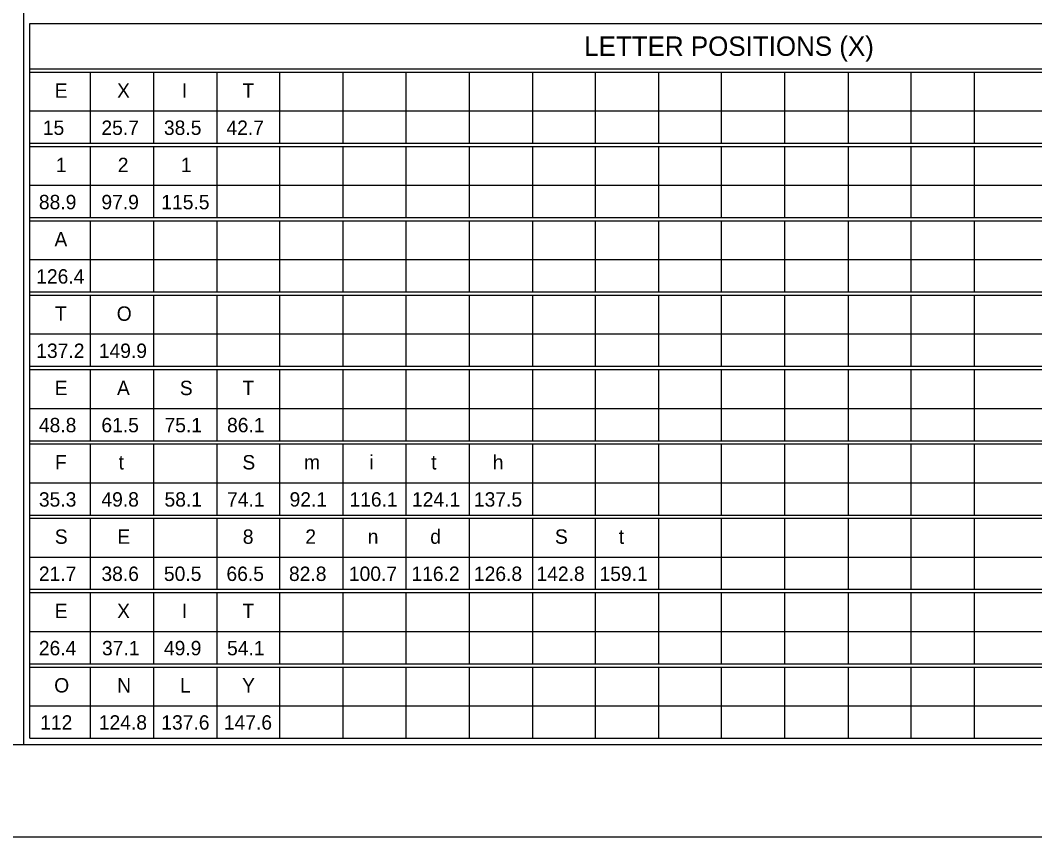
# Model space of a CAD drawing. Extents: x 2149934 to 2150188, y 145114 to 145238.
# Drawn here: x 2150076.2 to 2150112.58, y 145114.09 to 145143.36 of the extents above; entities that cross this region are included whole.
import ezdxf

# ---------------------------------------------------------------- set-up
doc = ezdxf.new("R2010")
doc.units = 0
for name, color, linetype in [('BORDER', 7, 'Continuous'), ('Level 1', 7, 'Continuous'), ('PDF', 7, 'Continuous')]:
    doc.layers.add(name, color=color, linetype=linetype)

msp = doc.modelspace()

# ---------------------------------------------------------------- linework, layer by layer
at = {"layer": 'BORDER'}
for p, q in [((2150017.557, 145117.388), (2150171.536, 145117.388)), ((2150010.458, 145114.088), (2150174.061, 145114.088))]:
    msp.add_line(p, q, dxfattribs=at)
at = {"layer": 'Level 1'}
for p, q in [((2150076.316, 145216.512), (2150076.316, 145117.388)), ((2150076.548, 145143.244), (2150134.843, 145143.244)), ((2150076.548, 145117.62), (2150076.548, 145143.244)), ((2150076.548, 145141.621), (2150134.843, 145141.621)), ((2150076.548, 145141.505), (2150134.843, 145141.505)), ((2150078.704, 145141.505), (2150078.704, 145138.954)), ((2150080.977, 145141.505), (2150080.977, 145138.954)), ((2150083.25, 145141.505), (2150083.25, 145138.954)), ((2150085.499, 145141.505), (2150085.499, 145138.954)), ((2150087.772, 145141.505), (2150087.772, 145138.954)), ((2150090.021, 145141.505), (2150090.021, 145138.954)), ((2150092.294, 145141.505), (2150092.294, 145138.954)), ((2150094.566, 145141.505), (2150094.566, 145138.954)), ((2150096.816, 145141.505), (2150096.816, 145138.954)), ((2150099.088, 145141.505), (2150099.088, 145138.954)), ((2150101.337, 145141.505), (2150101.337, 145138.954)), ((2150103.61, 145141.505), (2150103.61, 145138.954)), ((2150105.883, 145141.505), (2150105.883, 145138.954)), ((2150108.132, 145141.505), (2150108.132, 145138.954)), ((2150110.405, 145141.505), (2150110.405, 145138.954)), ((2150076.548, 145140.114), (2150126.185, 145140.114)), ((2150076.548, 145138.954), (2150134.843, 145138.954)), ((2150076.548, 145138.838), (2150134.843, 145138.838)), ((2150078.704, 145138.838), (2150078.704, 145136.288)), ((2150080.977, 145138.838), (2150080.977, 145136.288)), ((2150083.25, 145138.838), (2150083.25, 145136.288)), ((2150085.499, 145138.838), (2150085.499, 145136.288)), ((2150087.772, 145138.838), (2150087.772, 145136.288)), ((2150090.021, 145138.838), (2150090.021, 145136.288)), ((2150092.294, 145138.838), (2150092.294, 145136.288)), ((2150094.566, 145138.838), (2150094.566, 145136.288)), ((2150096.816, 145138.838), (2150096.816, 145136.288)), ((2150099.088, 145138.838), (2150099.088, 145136.288)), ((2150101.337, 145138.838), (2150101.337, 145136.288)), ((2150103.61, 145138.838), (2150103.61, 145136.288)), ((2150105.883, 145138.838), (2150105.883, 145136.288)), ((2150108.132, 145138.838), (2150108.132, 145136.288)), ((2150110.405, 145138.838), (2150110.405, 145136.288)), ((2150076.548, 145137.447), (2150126.185, 145137.447)), ((2150076.548, 145136.288), (2150134.843, 145136.288)), ((2150076.548, 145136.172), (2150134.843, 145136.172)), ((2150078.704, 145136.172), (2150078.704, 145133.621)), ((2150080.977, 145136.172), (2150080.977, 145133.621)), ((2150083.25, 145136.172), (2150083.25, 145133.621)), ((2150085.499, 145136.172), (2150085.499, 145133.621)), ((2150087.772, 145136.172), (2150087.772, 145133.621)), ((2150090.021, 145136.172), (2150090.021, 145133.621)), ((2150092.294, 145136.172), (2150092.294, 145133.621)), ((2150094.566, 145136.172), (2150094.566, 145133.621)), ((2150096.816, 145136.172), (2150096.816, 145133.621)), ((2150099.088, 145136.172), (2150099.088, 145133.621)), ((2150101.337, 145136.172), (2150101.337, 145133.621)), ((2150103.61, 145136.172), (2150103.61, 145133.621)), ((2150105.883, 145136.172), (2150105.883, 145133.621)), ((2150108.132, 145136.172), (2150108.132, 145133.621)), ((2150110.405, 145136.172), (2150110.405, 145133.621)), ((2150076.548, 145134.78), (2150126.185, 145134.78)), ((2150076.548, 145133.621), (2150134.843, 145133.621)), ((2150076.548, 145133.505), (2150134.843, 145133.505)), ((2150078.704, 145133.505), (2150078.704, 145130.954)), ((2150080.977, 145133.505), (2150080.977, 145130.954)), ((2150083.25, 145133.505), (2150083.25, 145130.954)), ((2150085.499, 145133.505), (2150085.499, 145130.954)), ((2150087.772, 145133.505), (2150087.772, 145130.954)), ((2150090.021, 145133.505), (2150090.021, 145130.954)), ((2150092.294, 145133.505), (2150092.294, 145130.954)), ((2150094.566, 145133.505), (2150094.566, 145130.954)), ((2150096.816, 145133.505), (2150096.816, 145130.954)), ((2150099.088, 145133.505), (2150099.088, 145130.954)), ((2150101.337, 145133.505), (2150101.337, 145130.954)), ((2150103.61, 145133.505), (2150103.61, 145130.954)), ((2150105.883, 145133.505), (2150105.883, 145130.954)), ((2150108.132, 145133.505), (2150108.132, 145130.954)), ((2150110.405, 145133.505), (2150110.405, 145130.954)), ((2150076.548, 145132.113), (2150126.185, 145132.113)), ((2150076.548, 145130.954), (2150134.843, 145130.954)), ((2150076.548, 145130.838), (2150134.843, 145130.838)), ((2150078.704, 145130.838), (2150078.704, 145128.287)), ((2150080.977, 145130.838), (2150080.977, 145128.287)), ((2150083.25, 145130.838), (2150083.25, 145128.287)), ((2150085.499, 145130.838), (2150085.499, 145128.287)), ((2150087.772, 145130.838), (2150087.772, 145128.287)), ((2150090.021, 145130.838), (2150090.021, 145128.287)), ((2150092.294, 145130.838), (2150092.294, 145128.287)), ((2150094.566, 145130.838), (2150094.566, 145128.287)), ((2150096.816, 145130.838), (2150096.816, 145128.287)), ((2150099.088, 145130.838), (2150099.088, 145128.287)), ((2150101.337, 145130.838), (2150101.337, 145128.287)), ((2150103.61, 145130.838), (2150103.61, 145128.287)), ((2150105.883, 145130.838), (2150105.883, 145128.287)), ((2150108.132, 145130.838), (2150108.132, 145128.287)), ((2150110.405, 145130.838), (2150110.405, 145128.287)), ((2150076.548, 145129.447), (2150126.185, 145129.447)), ((2150076.548, 145128.287), (2150134.843, 145128.287)), ((2150076.548, 145128.171), (2150134.843, 145128.171)), ((2150078.704, 145128.171), (2150078.704, 145125.62)), ((2150080.977, 145128.171), (2150080.977, 145125.62)), ((2150083.25, 145128.171), (2150083.25, 145125.62)), ((2150085.499, 145128.171), (2150085.499, 145125.62)), ((2150087.772, 145128.171), (2150087.772, 145125.62)), ((2150090.021, 145128.171), (2150090.021, 145125.62)), ((2150092.294, 145128.171), (2150092.294, 145125.62)), ((2150094.566, 145128.171), (2150094.566, 145125.62)), ((2150096.816, 145128.171), (2150096.816, 145125.62)), ((2150099.088, 145128.171), (2150099.088, 145125.62)), ((2150101.337, 145128.171), (2150101.337, 145125.62)), ((2150103.61, 145128.171), (2150103.61, 145125.62)), ((2150105.883, 145128.171), (2150105.883, 145125.62)), ((2150108.132, 145128.171), (2150108.132, 145125.62)), ((2150110.405, 145128.171), (2150110.405, 145125.62)), ((2150076.548, 145126.78), (2150126.185, 145126.78)), ((2150076.548, 145125.62), (2150134.843, 145125.62)), ((2150076.548, 145125.504), (2150134.843, 145125.504)), ((2150078.704, 145125.504), (2150078.704, 145122.954)), ((2150080.977, 145125.504), (2150080.977, 145122.954)), ((2150083.25, 145125.504), (2150083.25, 145122.954)), ((2150085.499, 145125.504), (2150085.499, 145122.954)), ((2150087.772, 145125.504), (2150087.772, 145122.954)), ((2150090.021, 145125.504), (2150090.021, 145122.954)), ((2150092.294, 145125.504), (2150092.294, 145122.954)), ((2150094.566, 145125.504), (2150094.566, 145122.954)), ((2150096.816, 145125.504), (2150096.816, 145122.954)), ((2150099.088, 145125.504), (2150099.088, 145122.954)), ((2150101.337, 145125.504), (2150101.337, 145122.954)), ((2150103.61, 145125.504), (2150103.61, 145122.954)), ((2150105.883, 145125.504), (2150105.883, 145122.954)), ((2150108.132, 145125.504), (2150108.132, 145122.954)), ((2150110.405, 145125.504), (2150110.405, 145122.954)), ((2150076.548, 145124.113), (2150126.185, 145124.113)), ((2150134.843, 145122.954), (2150076.548, 145122.954)), ((2150076.548, 145122.838), (2150134.843, 145122.838)), ((2150078.704, 145122.838), (2150078.704, 145120.287)), ((2150080.977, 145122.838), (2150080.977, 145120.287)), ((2150083.25, 145122.838), (2150083.25, 145120.287)), ((2150085.499, 145122.838), (2150085.499, 145120.287)), ((2150087.772, 145122.838), (2150087.772, 145120.287)), ((2150090.021, 145122.838), (2150090.021, 145120.287)), ((2150092.294, 145122.838), (2150092.294, 145120.287)), ((2150094.566, 145122.838), (2150094.566, 145120.287)), ((2150096.816, 145122.838), (2150096.816, 145120.287)), ((2150099.088, 145122.838), (2150099.088, 145120.287)), ((2150101.337, 145122.838), (2150101.337, 145120.287)), ((2150103.61, 145122.838), (2150103.61, 145120.287)), ((2150105.883, 145122.838), (2150105.883, 145120.287)), ((2150108.132, 145122.838), (2150108.132, 145120.287)), ((2150110.405, 145122.838), (2150110.405, 145120.287)), ((2150076.548, 145121.446), (2150126.185, 145121.446)), ((2150076.548, 145120.287), (2150134.843, 145120.287)), ((2150076.548, 145120.171), (2150134.843, 145120.171)), ((2150078.704, 145120.171), (2150078.704, 145117.62)), ((2150080.977, 145120.171), (2150080.977, 145117.62)), ((2150083.25, 145120.171), (2150083.25, 145117.62)), ((2150085.499, 145120.171), (2150085.499, 145117.62)), ((2150087.772, 145120.171), (2150087.772, 145117.62)), ((2150090.021, 145120.171), (2150090.021, 145117.62)), ((2150092.294, 145120.171), (2150092.294, 145117.62)), ((2150094.566, 145120.171), (2150094.566, 145117.62)), ((2150096.816, 145120.171), (2150096.816, 145117.62)), ((2150099.088, 145120.171), (2150099.088, 145117.62)), ((2150101.337, 145120.171), (2150101.337, 145117.62)), ((2150103.61, 145120.171), (2150103.61, 145117.62)), ((2150105.883, 145120.171), (2150105.883, 145117.62)), ((2150108.132, 145120.171), (2150108.132, 145117.62)), ((2150110.405, 145120.171), (2150110.405, 145117.62)), ((2150076.548, 145118.779), (2150126.185, 145118.779)), ((2150076.548, 145117.62), (2150134.843, 145117.62))]:
    msp.add_line(p, q, dxfattribs=at)
at = {"layer": 'PDF'}
msp.add_lwpolyline([(2150010.458, 145114.088), (2150174.061, 145114.088), (2150174.061, 145219.948), (2150010.458, 145219.948)], close=True, dxfattribs=at)

# ---------------------------------------------------------------- texts
at = {"layer": 'Level 1'}
for s, height, p in [('LETTER POSITIONS (X)', 0.69555, (2150096.422, 145142.085)), ('E', 0.517, (2150077.437, 145140.582)), ('X', 0.517, (2150079.67, 145140.582)), ('I', 0.517, (2150081.989, 145140.582)), ('T', 0.517, (2150084.167, 145140.582)), ('15', 0.5165, (2150077.008, 145139.25)), ('25.7', 0.5165, (2150079.109, 145139.25)), ('38.5', 0.5165, (2150081.351, 145139.25)), ('42.7', 0.5165, (2150083.593, 145139.25)), ('1', 0.517, (2150077.474, 145137.916)), ('2', 0.517, (2150079.695, 145137.916)), ('1', 0.517, (2150081.958, 145137.916)), ('88.9', 0.5165, (2150076.867, 145136.584)), ('97.9', 0.5165, (2150079.109, 145136.584)), ('115.5', 0.5165, (2150081.257, 145136.584)), ('A', 0.517, (2150077.425, 145135.251)), ('126.4', 0.5165, (2150076.771, 145133.919)), ('T', 0.517, (2150077.441, 145132.586)), ('O', 0.517, (2150079.658, 145132.585)), ('137.2', 0.5165, (2150076.773, 145131.253)), ('149.9', 0.5165, (2150079.015, 145131.253)), ('E', 0.517, (2150077.437, 145129.92)), ('A', 0.517, (2150079.667, 145129.92)), ('S', 0.517, (2150081.921, 145129.92)), ('T', 0.517, (2150084.167, 145129.92)), ('48.8', 0.5165, (2150076.867, 145128.588)), ('61.5', 0.5165, (2150079.109, 145128.588)), ('75.1', 0.5165, (2150081.372, 145128.588)), ('86.1', 0.5165, (2150083.614, 145128.588)), ('F', 0.517, (2150077.446, 145127.255)), ('t', 0.517, (2150079.726, 145127.255)), ('S', 0.517, (2150084.163, 145127.255)), ('m', 0.517, (2150086.372, 145127.255)), ('i', 0.517, (2150088.715, 145127.255)), ('t', 0.517, (2150090.935, 145127.255)), ('h', 0.517, (2150093.142, 145127.255)), ('35.3', 0.5165, (2150076.867, 145125.922)), ('49.8', 0.5165, (2150079.109, 145125.923)), ('58.1', 0.5165, (2150081.372, 145125.923)), ('74.1', 0.5165, (2150083.614, 145125.923)), ('92.1', 0.5165, (2150085.856, 145125.923)), ('116.1', 0.5165, (2150088.004, 145125.923)), ('124.1', 0.5165, (2150090.246, 145125.923)), ('137.5', 0.5165, (2150092.467, 145125.923)), ('S', 0.517, (2150077.437, 145124.589)), ('E', 0.517, (2150079.679, 145124.589)), ('8', 0.517, (2150084.179, 145124.589)), ('2', 0.517, (2150086.421, 145124.589)), ('n', 0.517, (2150088.658, 145124.589)), ('d', 0.517, (2150090.9, 145124.589)), ('S', 0.517, (2150095.372, 145124.589)), ('t', 0.517, (2150097.661, 145124.589)), ('21.7', 0.5165, (2150076.867, 145123.257)), ('38.6', 0.5165, (2150079.109, 145123.257)), ('50.5', 0.5165, (2150081.351, 145123.257)), ('66.5', 0.5165, (2150083.593, 145123.257)), ('82.8', 0.5165, (2150085.835, 145123.257)), ('100.7', 0.5165, (2150087.983, 145123.257)), ('116.2', 0.5165, (2150090.225, 145123.257)), ('126.8', 0.5165, (2150092.467, 145123.257)), ('142.8', 0.5165, (2150094.709, 145123.257)), ('159.1', 0.5165, (2150096.972, 145123.257)), ('E', 0.517, (2150077.437, 145121.924)), ('X', 0.517, (2150079.671, 145121.924)), ('I', 0.517, (2150081.989, 145121.924)), ('T', 0.517, (2150084.167, 145121.924)), ('26.4', 0.5165, (2150076.865, 145120.592)), ('37.1', 0.5165, (2150079.13, 145120.592)), ('49.9', 0.5165, (2150081.351, 145120.592)), ('54.1', 0.5165, (2150083.614, 145120.592)), ('O', 0.517, (2150077.416, 145119.258)), ('N', 0.517, (2150079.672, 145119.258)), ('L', 0.517, (2150081.925, 145119.258)), ('Y', 0.517, (2150084.154, 145119.258)), ('112', 0.5165, (2150076.914, 145117.926)), ('124.8', 0.5165, (2150079.015, 145117.926)), ('137.6', 0.5165, (2150081.257, 145117.926)), ('147.6', 0.5165, (2150083.499, 145117.926))]:
    msp.add_text(s, height=height, dxfattribs=at).set_placement(p)

doc.saveas('drawing.dxf')
